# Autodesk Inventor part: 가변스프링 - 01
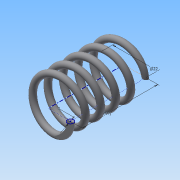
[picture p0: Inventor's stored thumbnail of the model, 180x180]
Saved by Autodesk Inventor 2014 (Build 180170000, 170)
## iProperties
Created: 2015-09
Part Number: 가변스프링 - 01
Material: 강철, 탄소
Document SubType Name: Modeling
Designer: study
Density: 7.87 g/cm^3
Appearance: 반연마
Mass: 18.8932 g
Surface Area: 32.5308 cm^2
Volume: 2.40066 cm^3
Author: study
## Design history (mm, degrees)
sketch "스케치1"
  geometry: L1 (0, 0)-(11, 0); L2 (11, 0)-(11, 40.245); L3 (11, 40.245)-(0, 40.245); L4 (0, 40.245)-(0, 0); C1 r 1.5 at (11, 0)
  constraints: 8 end point, 2 parallel, 1 centre point, 1 coincident, 1 horizontal, 1 perpendicular
  dimensions: "d0" = 22 diameter of L2 L4; "d1" = 40.2455 distance of L1.end L2.end (derived); "d2" = 3 diameter of C1
feature "코일1" sketch "스케치1" pitch "d3" = 10; turns "d5" = 5; dims "d4" = 40.2455 (= d1), "d6" = 0, angle "d7" = 90 deg, angle "d8" = 90 deg, "d9" = 0, "d10" = 0
node "작업 평면1"
sketch "스케치2"
  geometry: L1 (-12.5, 0)-(-9.5, 0) reference; 1 further point
  constraints: 1 horizontal alignment
extrude "돌출1" cut sketch "스케치2" stored distance "d12" = 10; taper "d13" = 0 deg
node "작업 평면2"
sketch "스케치3"
  geometry: L1 (-9.5, 0)-(-12.5, 0) reference; 1 further point
  constraints: 1 horizontal alignment
extrude "돌출2" cut sketch "스케치3" stored distance "d15" = 10; taper "d16" = 0 deg
node "솔리드1"
node "절단 모서리 투영1"
node "절단 모서리 투영2"
other parameters: "d11" = 0, "d14" = 40.2455 (= d1)
